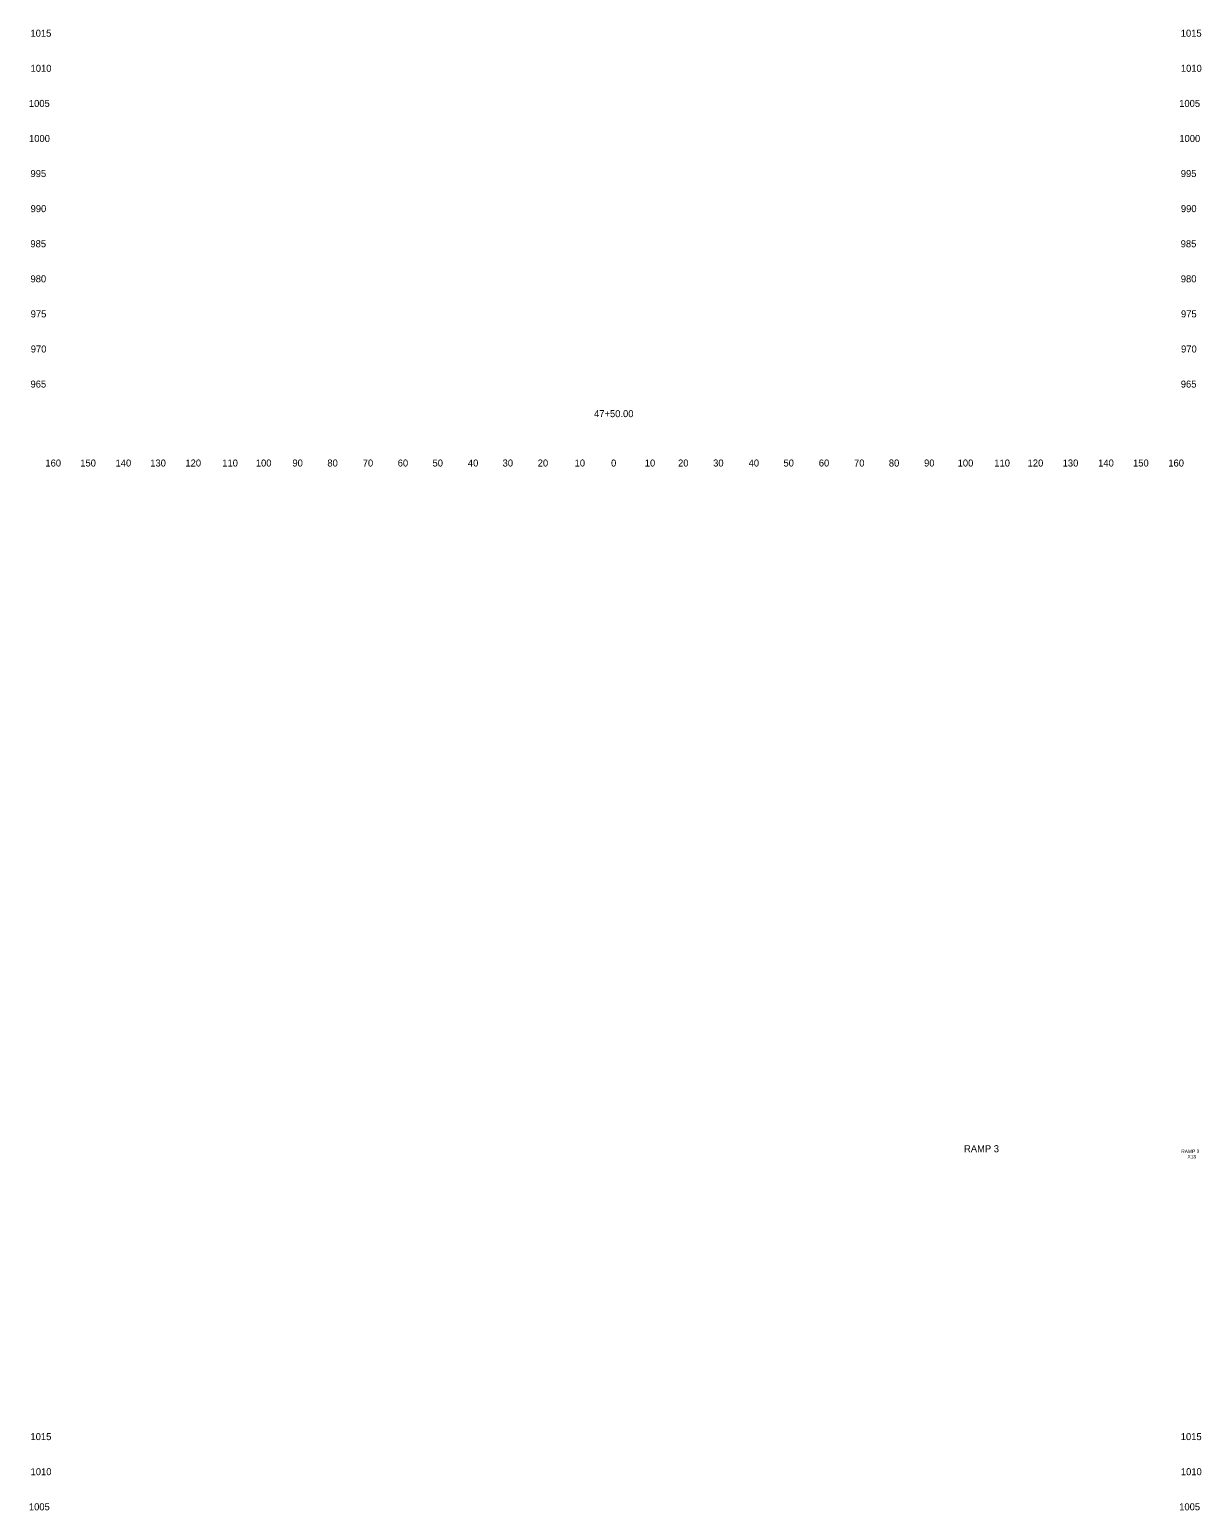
# Model space of a CAD drawing. Extents: x 4994 to 5843, y 4997 to 8804.
# Drawn here: x 5508.6 to 5842.5, y 7900 to 8322 of the extents above; entities that cross this region are included whole.
import ezdxf

# ---------------------------------------------------------------- set-up
doc = ezdxf.new("R2010")
doc.units = 0
for name, color, linetype in [('RD_SHT_ID', 7, 'Continuous'), ('RD_XS_TX_Offset', 7, 'Continuous'), ('RD_XS_TX_Station', 7, 'Continuous')]:
    doc.layers.add(name, color=color, linetype=linetype)

msp = doc.modelspace()

# ---------------------------------------------------------------- texts
at = {"layer": 'RD_SHT_ID'}
for s, height, p in [('RAMP 3', 2, (5774.89, 8002.06)), ('RAMP 3', 1, (5836.78, 8001.8)), ('X18', 1, (5838.57, 8000.3))]:
    msp.add_text(s, height=height, dxfattribs=at).set_placement(p)
at = {"layer": 'RD_XS_TX_Offset'}
for s, p in [('1015', (5508.85, 8320)), ('1015', (5836.65, 8320)), ('1010', (5508.88, 8310)), ('1010', (5836.68, 8310)), ('1005', (5508.4, 8300)), ('1005', (5836.2, 8300)), ('1000', (5508.44, 8290)), ('1000', (5836.24, 8290)), ('995', (5508.86, 8280)), ('995', (5836.66, 8280)), ('990', (5508.89, 8270)), ('990', (5836.69, 8270)), ('985', (5508.83, 8260)), ('985', (5836.63, 8260)), ('980', (5508.86, 8250)), ('980', (5836.66, 8250)), ('975', (5508.91, 8240)), ('975', (5836.71, 8240)), ('970', (5508.94, 8230)), ('970', (5836.74, 8230)), ('965', (5508.86, 8220)), ('965', (5836.66, 8220)), ('160', (5513.1, 8197.5)), ('150', (5523.04, 8197.5)), ('140', (5533.1, 8197.5)), ('130', (5542.99, 8197.5)), ('120', (5553.01, 8197.5)), ('110', (5563.51, 8197.5)), ('100', (5573.07, 8197.5)), ('90', (5583.5, 8197.5)), ('80', (5593.46, 8197.5)), ('70', (5603.54, 8197.5)), ('60', (5613.5, 8197.5)), ('50', (5623.43, 8197.5)), ('40', (5633.5, 8197.5)), ('30', (5643.39, 8197.5)), ('20', (5653.4, 8197.5)), ('10', (5663.91, 8197.5)), ('0', (5674.3, 8197.5)), ('0', (5674.3, 8197.5)), ('10', (5683.91, 8197.5)), ('20', (5693.4, 8197.5)), ('30', (5703.39, 8197.5)), ('40', (5713.5, 8197.5)), ('50', (5723.43, 8197.5)), ('60', (5733.5, 8197.5)), ('70', (5743.54, 8197.5)), ('80', (5753.46, 8197.5)), ('90', (5763.5, 8197.5)), ('100', (5773.07, 8197.5)), ('110', (5783.51, 8197.5)), ('120', (5793.01, 8197.5)), ('130', (5802.99, 8197.5)), ('140', (5813.1, 8197.5)), ('150', (5823.04, 8197.5)), ('160', (5833.1, 8197.5)), ('1015', (5508.85, 7920)), ('1015', (5836.65, 7920)), ('1010', (5508.88, 7910)), ('1010', (5836.68, 7910)), ('1005', (5508.4, 7900)), ('1005', (5836.2, 7900))]:
    msp.add_text(s, height=2, dxfattribs=at).set_placement(p)
at = {"layer": 'RD_XS_TX_Station'}
msp.add_text('47+50.00', height=2, dxfattribs=at).set_placement((5669.46, 8211.57))

doc.saveas('drawing.dxf')
